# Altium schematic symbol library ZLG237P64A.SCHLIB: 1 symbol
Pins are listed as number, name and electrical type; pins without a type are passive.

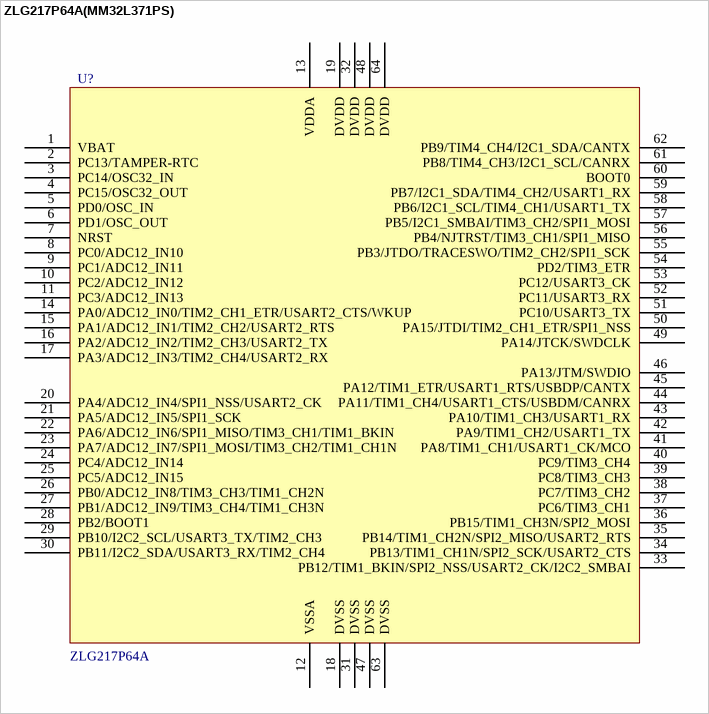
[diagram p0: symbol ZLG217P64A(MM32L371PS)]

## ZLG217P64A(MM32L371PS)
designator U?, comment ZLG217P64A
ZLG217P64A,LQFP64,ZLG; 物料代码: 1.05.02.0207; 名称: 集成电路; 贴片和直插: SMT; PCB备注: 171017lmd; 器件优选方案: 正常状态，可以选用
footprint ZLG237P64A
pins: 1 VBAT (power), 2 PC13/TAMPER-RTC, 3 PC14/OSC32_IN, 4 PC15/OSC32_OUT, 5 PD0/OSC_IN (power), 6 PD1/OSC_OUT, 7 NRST, 8 PC0/ADC12_IN10, 9 PC1/ADC12_IN11, 10 PC2/ADC12_IN12, 11 PC3/ADC12_IN13, 12 VSSA, 13 VDDA, 14 PA0/ADC12_IN0/TIM2_CH1_ETR/USART2_CTS/WKUP, 15 PA1/ADC12_IN1/TIM2_CH2/USART2_RTS, 16 PA2/ADC12_IN2/TIM2_CH3/USART2_TX, 17 PA3/ADC12_IN3/TIM2_CH4/USART2_RX (power), 18 DVSS, 19 DVDD, 20 PA4/ADC12_IN4/SPI1_NSS/USART2_CK, 21 PA5/ADC12_IN5/SPI1_SCK, 22 PA6/ADC12_IN6/SPI1_MISO/TIM3_CH1/TIM1_BKIN, 23 PA7/ADC12_IN7/SPI1_MOSI/TIM3_CH2/TIM1_CH1N, 24 PC4/ADC12_IN14, 25 PC5/ADC12_IN15, 26 PB0/ADC12_IN8/TIM3_CH3/TIM1_CH2N, 27 PB1/ADC12_IN9/TIM3_CH4/TIM1_CH3N, 28 PB2/BOOT1, 29 PB10/I2C2_SCL/USART3_TX/TIM2_CH3, 30 PB11/I2C2_SDA/USART3_RX/TIM2_CH4, 31 DVSS, 32 DVDD, 33 PB12/TIM1_BKIN/SPI2_NSS/USART2_CK/I2C2_SMBAI, 34 PB13/TIM1_CH1N/SPI2_SCK/USART2_CTS, 35 PB14/TIM1_CH2N/SPI2_MISO/USART2_RTS, 36 PB15/TIM1_CH3N/SPI2_MOSI, 37 PC6/TIM3_CH1, 38 PC7/TIM3_CH2, 39 PC8/TIM3_CH3, 40 PC9/TIM3_CH4, 41 PA8/TIM1_CH1/USART1_CK/MCO, 42 PA9/TIM1_CH2/USART1_TX, 43 PA10/TIM1_CH3/USART1_RX, 44 PA11/TIM1_CH4/USART1_CTS/USBDM/CANRX (power), 45 PA12/TIM1_ETR/USART1_RTS/USBDP/CANTX, 46 PA13/JTM/SWDIO, 47 DVSS, 48 DVDD, 49 PA14/JTCK/SWDCLK, 50 PA15/JTDI/TIM2_CH1_ETR/SPI1_NSS, 51 PC10/USART3_TX (power), 52 PC11/USART3_RX, 53 PC12/USART3_CK, 54 PD2/TIM3_ETR, 55 PB3/JTDO/TRACESWO/TIM2_CH2/SPI1_SCK (power), 56 PB4/NJTRST/TIM3_CH1/SPI1_MISO, 57 PB5/I2C1_SMBAI/TIM3_CH2/SPI1_MOSI, 58 PB6/I2C1_SCL/TIM4_CH1/USART1_TX, 59 PB7/I2C1_SDA/TIM4_CH2/USART1_RX, 60 BOOT0, 61 PB8/TIM4_CH3/I2C1_SCL/CANRX, 62 PB9/TIM4_CH4/I2C1_SDA/CANTX, 63 DVSS, 64 DVDD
